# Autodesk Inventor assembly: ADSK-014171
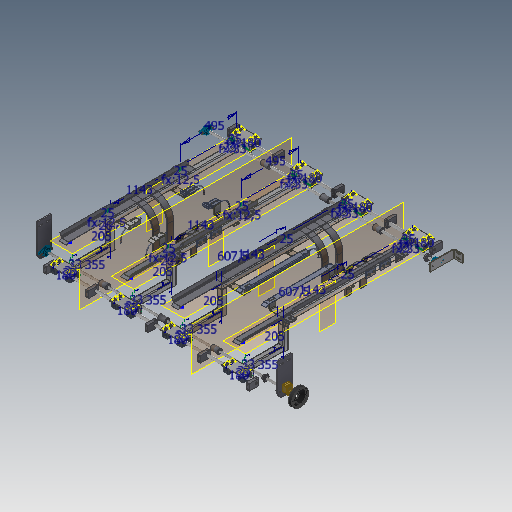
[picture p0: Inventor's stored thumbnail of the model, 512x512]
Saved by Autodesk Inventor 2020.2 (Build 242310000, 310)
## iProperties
Created: 2019-10
Part Number: ADSK-014171
Document SubType Name: Assembly
Designer: lutzd
Mass: 130307 g
Surface Area: 71619.2 cm^2
Volume: 22224.3 cm^3
Density: 5.86325 g/cm^3
VLDS_Profile: Default Assembly
VLDS_TimeStamp: 2016-07-29
VLDS_FailCnt: 0
VLDS_AcceptCnt: 0
Dimensions: 1749x369,4x2340,3 mm
Mass: 130,307 kg
DocNumber: ADSK-014171
Folder: 01 - Themengebiete\Simplification\01 - Packaging machine\
VDS_Category: 3D Komponenten
VDS_NumSchm: Autodesk
Title: SUB-159310
Author: lutzd
Revision Number: -
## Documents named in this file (49)
- D:\07 - DEMODATEN\OTX 2019 - Dataset - UPDATE - Dez2019\Designs\07-Packing machine\ADSK-014171.iam
- D:\07 - DEMODATEN\OTX 2019 - Dataset - UPDATE - Dez2019\Designs\07-Packing machine\Parts\ADSK-011683.ipt
- D:\07 - DEMODATEN\OTX 2019 - Dataset - UPDATE - Dez2019\Designs\07-Packing machine\Parts\ADSK-011686.ipt
- D:\07 - DEMODATEN\OTX 2019 - Dataset - UPDATE - Dez2019\Designs\07-Packing machine\Parts\ADSK-011714.ipt
- D:\07 - DEMODATEN\OTX 2019 - Dataset - UPDATE - Dez2019\Content Center Files\de-DE\DIN 125-1  B\DIN 125-1 - B 8,4.ipt
- D:\07 - DEMODATEN\OTX 2019 - Dataset - UPDATE - Dez2019\Designs\07-Packing machine\Parts\ADSK-011768.ipt
- D:\07 - DEMODATEN\OTX 2019 - Dataset - UPDATE - Dez2019\Designs\07-Packing machine\Parts\ADSK-011336.ipt
- D:\07 - DEMODATEN\OTX 2019 - Dataset - UPDATE - Dez2019\Designs\07-Packing machine\Parts\ADSK-011726.ipt
- D:\07 - DEMODATEN\OTX 2019 - Dataset - UPDATE - Dez2019\Designs\07-Packing machine\Parts\ADSK-011337.ipt
- D:\07 - DEMODATEN\OTX 2019 - Dataset - UPDATE - Dez2019\Designs\07-Packing machine\Parts\ADSK-011339.ipt
- D:\07 - DEMODATEN\OTX 2019 - Dataset - UPDATE - Dez2019\Designs\07-Packing machine\Parts\ADSK-011723.ipt
- D:\07 - DEMODATEN\OTX 2019 - Dataset - UPDATE - Dez2019\Content Center Files\de-DE\ISO 2491 - A\ISO 2491 - A  5 x 3 x 32.ipt
- D:\07 - DEMODATEN\OTX 2019 - Dataset - UPDATE - Dez2019\Designs\07-Packing machine\Parts\ADSK-011309.ipt
- D:\07 - DEMODATEN\OTX 2019 - Dataset - UPDATE - Dez2019\Content Center Files\de-DE\ISO 2491 - A\ISO 2491 - A  5 x 3 x 16.ipt
- D:\07 - DEMODATEN\OTX 2019 - Dataset - UPDATE - Dez2019\Content Center Files\de-DE\ISO 4028\ISO 4028 - M5 x 6 - ISO.ipt
- D:\07 - DEMODATEN\OTX 2019 - Dataset - UPDATE - Dez2019\Content Center Files\de-DE\ISO 4028\ISO 4028 - M5 x 10 - ISO.ipt
- D:\07 - DEMODATEN\OTX 2019 - Dataset - UPDATE - Dez2019\Designs\07-Packing machine\500277.iam
- D:\07 - DEMODATEN\OTX 2019 - Dataset - UPDATE - Dez2019\Designs\07-Packing machine\Parts\ADSK-011325.ipt
- D:\07 - DEMODATEN\OTX 2019 - Dataset - UPDATE - Dez2019\Designs\07-Packing machine\ADSK-014191.iam
- D:\07 - DEMODATEN\OTX 2019 - Dataset - UPDATE - Dez2019\Designs\07-Packing machine\Parts\ADSK-014197.ipt
- D:\07 - DEMODATEN\OTX 2019 - Dataset - UPDATE - Dez2019\Designs\07-Packing machine\Parts\ADSK-011328.ipt
- D:\07 - DEMODATEN\OTX 2019 - Dataset - UPDATE - Dez2019\Content Center Files\de-DE\ISO 4762(2)\ISO 4762 - M8 x 25ISO.ipt
- D:\07 - DEMODATEN\OTX 2019 - Dataset - UPDATE - Dez2019\Content Center Files\de-DE\ISO 4762(2)\ISO 4762 - M8 x 80ISO.ipt
- D:\07 - DEMODATEN\OTX 2019 - Dataset - UPDATE - Dez2019\Content Center Files\de-DE\ISO 4762(2)\ISO 4762 - M8 x 65ISO.ipt
- D:\07 - DEMODATEN\OTX 2019 - Dataset - UPDATE - Dez2019\Content Center Files\de-DE\ISO 4032(1)\ISO 4032 - M8DIN EN.ipt
- D:\07 - DEMODATEN\OTX 2019 - Dataset - UPDATE - Dez2019\Designs\07-Packing machine\Parts\ADSK-011684.ipt
- D:\07 - DEMODATEN\OTX 2019 - Dataset - UPDATE - Dez2019\Designs\07-Packing machine\Parts\ADSK-011685.ipt
- D:\07 - DEMODATEN\OTX 2019 - Dataset - UPDATE - Dez2019\Designs\07-Packing machine\500249.iam
- D:\07 - DEMODATEN\OTX 2019 - Dataset - UPDATE - Dez2019\Designs\07-Packing machine\500382.iam
- D:\07 - DEMODATEN\OTX 2019 - Dataset - UPDATE - Dez2019\Designs\07-Packing machine\500380R.iam
- D:\07 - DEMODATEN\OTX 2019 - Dataset - UPDATE - Dez2019\Designs\07-Packing machine\500380L.iam
- D:\07 - DEMODATEN\OTX 2019 - Dataset - UPDATE - Dez2019\Designs\07-Packing machine\500400R.iam
- D:\07 - DEMODATEN\OTX 2019 - Dataset - UPDATE - Dez2019\Designs\07-Packing machine\500400L.iam
- D:\07 - DEMODATEN\OTX 2019 - Dataset - UPDATE - Dez2019\Designs\07-Packing machine\Parts\ADSK-011326.ipt
- D:\07 - DEMODATEN\OTX 2019 - Dataset - UPDATE - Dez2019\Designs\07-Packing machine\Parts\ADSK-011327.ipt
- D:\07 - DEMODATEN\OTX 2019 - Dataset - UPDATE - Dez2019\Designs\07-Packing machine\500579.iam
- D:\07 - DEMODATEN\OTX 2019 - Dataset - UPDATE - Dez2019\Content Center Files\de-DE\ISO 4762(2)\ISO 4762 - M8 x 16ISO.ipt
- D:\07 - DEMODATEN\OTX 2019 - Dataset - UPDATE - Dez2019\Content Center Files\de-DE\ISO 4762(2)\ISO 4762 - M12 x 30ISO.ipt
- D:\07 - DEMODATEN\OTX 2019 - Dataset - UPDATE - Dez2019\Designs\07-Packing machine\500369.iam
- D:\07 - DEMODATEN\OTX 2019 - Dataset - UPDATE - Dez2019\Designs\07-Packing machine\Parts\ADSK-011509.ipt
- D:\07 - DEMODATEN\OTX 2019 - Dataset - UPDATE - Dez2019\Designs\07-Packing machine\Parts\ADSK-011508.ipt
- D:\07 - DEMODATEN\OTX 2019 - Dataset - UPDATE - Dez2019\Designs\07-Packing machine\Parts\ADSK-011312.ipt
- D:\07 - DEMODATEN\OTX 2019 - Dataset - UPDATE - Dez2019\Content Center Files\de-DE\ISO 4028\ISO 4028 - M5 x 16 - ISO.ipt
- D:\07 - DEMODATEN\OTX 2019 - Dataset - UPDATE - Dez2019\Content Center Files\de-DE\ISO 10642(1)\ISO 10642 - M4x10.ipt
- D:\07 - DEMODATEN\OTX 2019 - Dataset - UPDATE - Dez2019\Designs\07-Packing machine\Parts\ADSK-011510.ipt
- D:\07 - DEMODATEN\OTX 2019 - Dataset - UPDATE - Dez2019\Designs\07-Packing machine\Parts\ADSK-011511.ipt
- D:\07 - DEMODATEN\OTX 2019 - Dataset - UPDATE - Dez2019\Designs\07-Packing machine\Parts\ADSK-011512.ipt
- D:\07 - DEMODATEN\OTX 2019 - Dataset - UPDATE - Dez2019\Content Center Files\de-DE\DIN 125-1  B\DIN 125-1 - B 4,3.ipt
- D:\07 - DEMODATEN\OTX 2019 - Dataset - UPDATE - Dez2019\Content Center Files\de-DE\ISO 4762(2)\ISO 4762 - M4 x 10ISO.ipt
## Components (377 placed, 48 different names)
1. ADSK-011683:1 — Passend:1, Passend:2, Passend:4, Fluchtend:2, Passend:7, Passend:8, Passend:9, Passend:19, Fluchtend:97
2. ADSK-011686:1 — Passend:3, Passend:4, Fluchtend:2, Passend:5, Passend:6, Passend:10, Passend:11, Passend:16, Passend:17, Passend:18, Passend:34
3. ADSK-011714:1 — Passend:6, Passend:10, Passend:11, Fluchtend:104
4. ADSK-011714:2 — Passend:7, Passend:8, Passend:9, Passend:20
5. ADSK-011768:1 — Passend:16, Passend:17, Passend:18, Passend:40
6. ADSK-011336:1 — Passend:19, Passend:20, Passend:26
7. ADSK-011726:1 — Passend:21, Passend:26, Passend:27, Fluchtend:89, Passend:89
8. ADSK-011726:2 — Passend:22, Fluchtend:10, Passend:28, Fluchtend:52, Passend:90
9. ADSK-011726:3 — Passend:23, Passend:29, Passend:31, Fluchtend:51, Passend:88
10. ADSK-011337:1 — Passend:24, Passend:27, Passend:28, Passend:89
11. ADSK-014197:2 — Passend:25, Passend:29, Passend:52, Passend:90
12. ADSK-011339:1 — Passend:30, Passend:31, Passend:33, Passend:36, Passend:37, Passend:38, Passend:39, Passend:42, Passend:44, Fluchtend:44, Fluchtend:45, Passend:45, Tangential:1, Passend:51, Passend:88
13. ADSK-011723:1 — Passend:33, Passend:34, Passend:45, Passend:47, Fluchtend:103, ROTATION
14. ADSK-011309:1 — Passend:39, Passend:40, Fluchtend:45, Passend:46
15. 500277:1 [sub-assembly] — Passend:52, Passend:54, Passend:61, Passend:62, Passend:63, Passend:64, Passend:65, Passend:66, Passend:87, Passend:148, Passend:149, Passend:152, Passend:153, Passend:243, Passend:269, Passend:270, Passend:271, Passend:272, Passend:273, Passend:274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
16. 500277:2 [sub-assembly] — Passend:51, Passend:53, Passend:55, Passend:56, Passend:57, Passend:58, Passend:59, Passend:60, Passend:86, Passend:142, Passend:143, Passend:146, Passend:147, Passend:263, Passend:264, Passend:265, Passend:266, Passend:267, Passend:268, Passend:287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
17. ADSK-011325:1 — Passend:61, Passend:62, Passend:63, Passend:115
18. ADSK-011325:2 — Passend:58, Passend:59, Passend:60
19. ADSK-011325:3 — Passend:55, Passend:56, Passend:57
20. ADSK-011325:4 — Passend:64, Passend:65, Passend:66
21. ADSK-011325:5 — Passend:143, Passend:144, Passend:146
22. ADSK-011325:6 — Passend:142, Passend:145, Passend:147
23. ADSK-011325:7 — Passend:149, Passend:151, Passend:152
24. ADSK-011325:8 — Passend:148, Passend:150, Passend:153
25. ADSK-014191:1 [sub-assembly] — Passend:80, Passend:82, Passend:85, Passend:136, Passend:137, Passend:140, Passend:141, Passend:160, Passend:161, Passend:164, Passend:165, Passend:250, Passend:281, Passend:282, Passend:283, Passend:284, Passend:285, Passend:286, Passend:299, Passend:300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
26. ADSK-014191:2 [sub-assembly] — Passend:79, Passend:81, Passend:84, Passend:130, Passend:132, Passend:133, Passend:135, Passend:154, Passend:155, Passend:158, Passend:159, Passend:275, Passend:276, Passend:277, Passend:278, Passend:279, Passend:280, Passend:305, Passend:306, Passend:307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
27. ADSK-011325:9 — Passend:130, Passend:131, Passend:132
28. ADSK-011325:10 — Passend:133, Passend:134, Passend:135
29. ADSK-011325:11 — Passend:136, Passend:139, Passend:140
30. ADSK-011325:12 — Passend:137, Passend:138, Passend:141
31. ADSK-011325:13 — Passend:155, Passend:156, Passend:159
32. ADSK-011325:14 — Passend:154, Passend:157, Passend:158
33. ADSK-011325:15 — Passend:161, Passend:162, Passend:165
34. ADSK-011325:16 — Passend:160, Passend:163, Passend:164
35. ADSK-011326:3 — Passend:115, Einfügen:8, Fluchtend:90, Passend:124, Passend:125, Passend:126, Passend:131, Passend:134, Passend:138, Passend:139, Einfügen:99
36. ADSK-011327:5 — Winkel:2, Fluchtend:94, Fluchtend:95, Fluchtend:96, Einfügen:99
37. ADSK-011327:6 — Einfügen:8, Winkel:1
38. ADSK-011326:4 — Einfügen:9, Einfügen:10, Passend:117, Passend:118, Passend:119, Passend:120, Passend:144, Passend:145, Passend:150, Passend:151, Passend:156, Passend:157, Passend:162, Passend:163
39. ADSK-011327:7 — Einfügen:9, Winkel:3, Fluchtend:93
40. ADSK-011327:8 — Einfügen:10, Winkel:4
41. ADSK-011328:1 — Passend:118, Fluchtend:91, Fluchtend:93, Passend:121
42. ADSK-011328:2 — Passend:119, Fluchtend:91, Fluchtend:92, Passend:122
43. ADSK-011328:3 — Passend:120, Fluchtend:92, Passend:123
44. ADSK-011328:4 — Passend:124, Fluchtend:96, Passend:127
45. ADSK-011328:5 — Passend:125, Fluchtend:95, Passend:128
46. ADSK-011328:6 — Passend:126, Fluchtend:94, Passend:129
47. ADSK-011714:3 — Fluchtend:97, Passend:250, Passend:258
48. ADSK-011336:2 — Passend:247, Fluchtend:99
49. ADSK-011726:4 — Passend:244, Passend:247, Fluchtend:98
50. ADSK-011726:5 — Passend:245, Passend:246, Fluchtend:100, Fluchtend:102
51. ADSK-011726:6 — Passend:249, Fluchtend:101, Passend:251, Passend:252, Passend:253
52. ADSK-011337:2 — Passend:243, Passend:244, Passend:245
53. ADSK-014197:3 — Passend:246, Passend:248, Passend:249, Fluchtend:102
54. ADSK-011723:2 — Passend:248, Fluchtend:103, ROTATION
55. ADSK-011684:1 — Passend:251, Passend:252, Passend:253, Passend:254, Passend:255, Passend:256, Passend:257
56. ADSK-011714:4 — Passend:257, Fluchtend:104, Passend:258, Passend:259, Passend:260
57. ADSK-011685:1 — Passend:259, Passend:260, Passend:261, Passend:262
58. 500249:1 [sub-assembly] — Passend:269, Passend:270, Passend:271, Passend:364, Passend:366
59. 500249:2 [sub-assembly] — Passend:263, Passend:267, Passend:268, Passend:344, Passend:346
60. 500249:3 [sub-assembly] — Passend:264, Passend:265, Passend:266, Passend:348, Passend:350
61. 500249:4 [sub-assembly] — Passend:275, Passend:276, Passend:277, Passend:380, Passend:382
62. 500249:5 [sub-assembly] — Passend:272, Passend:273, Passend:274, Passend:360, Passend:362
63. 500249:6 [sub-assembly] — Passend:278, Passend:279, Passend:280, Passend:376, Passend:378
64. 500249:7 [sub-assembly] — Passend:282, Passend:285, Passend:286, Passend:392, Passend:394
65. 500249:8 [sub-assembly] — Passend:281, Passend:283, Passend:284, Passend:396, Passend:398
66. 500382:1 [sub-assembly] — Passend:287, Passend:288, Passend:289, Passend:320, Passend:352, Passend:354
67. 500382:2 [sub-assembly] — Passend:290, Passend:291, Passend:292, Passend:318, Passend:319, Passend:340, Passend:342
68. 500382:3 [sub-assembly] — Passend:293, Passend:294, Passend:295, Passend:315, Passend:356, Passend:358
69. 500382:4 [sub-assembly] — Passend:296, Passend:297, Passend:298, Fluchtend:107, Passend:316, Passend:368, Passend:370
70. 500382:5 [sub-assembly] — Passend:299, Passend:301, Passend:302, Passend:311, Passend:312, Passend:400, Passend:402, Fluchtend:435
71. 500382:6 [sub-assembly] — Passend:300, Passend:303, Passend:304, Passend:313, Passend:388, Passend:390
72. 500382:7 [sub-assembly] — Passend:305, Passend:309, Passend:310, Passend:314, Fluchtend:105, Passend:384, Passend:386
73. 500382:8 [sub-assembly] — Passend:306, Passend:307, Passend:308, Passend:317, Passend:372, Passend:374
74. 500380R:1 [sub-assembly] — Passend:311, Passend:312, Passend:313, Passend:327, Passend:539, Passend:541, Fluchtend:435
75. 500380L:1 [sub-assembly] — Passend:314, Fluchtend:105, Passend:317, Passend:326, Passend:330, Passend:535, Passend:537
76. 500400R:1 [sub-assembly] — Passend:315, Fluchtend:107, Passend:316, Passend:325, Fluchtend:108, Passend:543, Passend:545
77. 500400L:1 [sub-assembly] — Passend:318, Passend:319, Passend:320, Passend:328, Passend:547, Passend:549, Passend:550
78. 500579:1 [sub-assembly] — Passend:321, Passend:337, Passend:338, Passend:411, Passend:412, Passend:413, Passend:441, Passend:443
79. 500579:4 [sub-assembly] — Passend:324, Passend:331, Passend:332, Passend:415, Passend:418, Passend:429, Passend:431
80. 500369:1 [sub-assembly] — Passend:406, Passend:407, Passend:408, Passend:414, Passend:419, Fluchtend:111, Passend:421, Fluchtend:423, Passend:437, Passend:439
81. 500369:2 [sub-assembly] — Passend:405, Passend:409, Passend:410, Passend:416, Passend:417, Passend:420, Fluchtend:110, Passend:422, Passend:424, Passend:433, Passend:435
82. ADSK-011509:1 — Passend:411, Passend:412, Passend:413, Passend:414, Fluchtend:424
83. ADSK-011508:1 — Passend:415, Passend:416, Passend:417, Passend:418, Passend:427
84. ADSK-011312:1 — Passend:420, Fluchtend:110, Passend:422, Passend:426
85. ADSK-011312:2 — Passend:419, Fluchtend:111, Passend:421, Fluchtend:423, Passend:425
86. 500369:3 [sub-assembly] — Passend:455, Passend:456, Passend:457, Fluchtend:426, Passend:479, Passend:483, Passend:485, Passend:487, Passend:492, Fluchtend:427, Fluchtend:431, Passend:497, Passend:514, Passend:517, Fluchtend:433
87. 500369:4 [sub-assembly] — Passend:454, Passend:458, Passend:459, Fluchtend:425, Passend:491, Passend:495, Fluchtend:429, Passend:499, Passend:507, Passend:508, Passend:509
88. 500369:5 [sub-assembly] — Passend:453, Passend:462, Passend:463, Passend:465, Passend:467, Passend:471, Passend:473, Passend:475, Passend:493, Passend:494, Fluchtend:432, Passend:496, Passend:515, Passend:516, Fluchtend:434
89. 500369:6 [sub-assembly] — Passend:452, Passend:460, Passend:461, Passend:464, Passend:490, Fluchtend:428, Fluchtend:430, Passend:498, Passend:504, Passend:505, Passend:506
90. ADSK-011312:3 — Passend:492, Fluchtend:427, Fluchtend:431, Passend:500
91. ADSK-011312:4 — Passend:493, Passend:494, Fluchtend:432, Passend:503
92. ADSK-011312:5 — Passend:491, Passend:495, Fluchtend:429, Passend:502
93. ADSK-011312:6 — Passend:490, Fluchtend:428, Fluchtend:430, Passend:501
94. ADSK-011510:1 — Passend:504, Passend:505, Passend:506
95. ADSK-011511:1 — Passend:507, Passend:508, Passend:509
96. ADSK-011512:1 — Passend:514, Passend:517, Fluchtend:433, Passend:523, Passend:525
97. ADSK-011512:2 — Passend:515, Passend:516, Fluchtend:434, Passend:519, Passend:521
98. DIN 125-1 B B 8,4:98 — Einfügen:161
99. DIN 125-1 B B 8,4:99 — Einfügen:162
100. DIN 125-1 B B 4,3:1 — Passend:519, Passend:531, Passend:533
101. DIN 125-1 B B 4,3:2 — Passend:521
102. DIN 125-1 B B 4,3:3 — Passend:523, Passend:527, Passend:529
103. DIN 125-1 B B 4,3:4 — Passend:525
104. ISO 4762 M4 x 10:1 — Passend:527
105. ISO 4762 M4 x 10:2 — Passend:529
106. ISO 4762 M4 x 10:3 — Passend:531
107. ISO 4762 M4 x 10:4 — Passend:533
108. DIN 125-1 B B 8,4:90 — Passend:535
109. DIN 125-1 B B 8,4:91 — Passend:537
110. DIN 125-1 B B 8,4:92 — Passend:539
111. DIN 125-1 B B 8,4:93 — Passend:541
112. DIN 125-1 B B 8,4:94 — Passend:543
113. DIN 125-1 B B 8,4:95 — Passend:545
114. DIN 125-1 B B 8,4:96 — Passend:547
115. DIN 125-1 B B 8,4:97 — Passend:549
116. ISO 4762 M8 x 16:49
117. ISO 4762 M8 x 16:50
118. ISO 4762 M8 x 16:51
119. ISO 4762 M8 x 16:52
120. ISO 4762 M8 x 16:53
121. ISO 4762 M8 x 16:54
122. ISO 4762 M8 x 16:55
123. ISO 4762 M8 x 16:56
124. ISO 10642 M4x10:9
125. ISO 10642 M4x10:10
126. ISO 10642 M4x10:11
127. ISO 10642 M4x10:12
128. DIN 125-1 B B 8,4:79 — Passend:467, Einfügen:143
129. DIN 125-1 B B 8,4:81 — Passend:471
130. DIN 125-1 B B 8,4:82 — Passend:473, Einfügen:146
131. DIN 125-1 B B 8,4:83 — Passend:475, Einfügen:145
132. DIN 125-1 B B 8,4:85 — Passend:479, Einfügen:147
133. DIN 125-1 B B 8,4:87 — Passend:483, Einfügen:148
134. DIN 125-1 B B 8,4:88 — Passend:485, Einfügen:150
135. DIN 125-1 B B 8,4:89 — Passend:487, Einfügen:149
136. ISO 4762 M8 x 16:41 — Einfügen:143
137. ISO 4762 M8 x 16:42
138. ISO 4762 M8 x 16:43 — Einfügen:146
139. ISO 4762 M8 x 16:44 — Einfügen:145
140. ISO 4762 M8 x 16:45 — Einfügen:147
141. ISO 4762 M8 x 16:46 — Einfügen:148
142. ISO 4762 M8 x 16:47 — Einfügen:149
143. ISO 4762 M8 x 16:48 — Einfügen:150
144. ISO 4028 M5 x 16:3 — Passend:497, Passend:500
145. ISO 4028 M5 x 16:4 — Passend:496, Passend:503
146. ISO 4028 M5 x 16:5 — Passend:499, Passend:502
147. ISO 4028 M5 x 16:6 — Passend:498, Passend:501
148. ISO 4028 M5 x 16:1 — Passend:425
149. ISO 4028 M5 x 16:2 — Passend:424, Passend:426
150. DIN 125-1 B B 8,4:71 — Passend:429, Einfügen:142
151. DIN 125-1 B B 8,4:72 — Passend:431, Einfügen:141
152. DIN 125-1 B B 8,4:73 — Passend:433, Einfügen:140
153. DIN 125-1 B B 8,4:74 — Passend:435, Einfügen:139
154. DIN 125-1 B B 8,4:75 — Passend:437, Einfügen:138
155. DIN 125-1 B B 8,4:76 — Passend:439, Einfügen:137
156. DIN 125-1 B B 8,4:77 — Passend:441, Einfügen:136
157. DIN 125-1 B B 8,4:78 — Passend:443, Einfügen:135
158. ISO 4762 M8 x 16:33 — Einfügen:135
159. ISO 4762 M8 x 16:34 — Einfügen:136
160. ISO 4762 M8 x 16:35 — Einfügen:138
161. ISO 4762 M8 x 16:36 — Einfügen:137
162. ISO 4762 M8 x 16:37 — Einfügen:142
163. ISO 4762 M8 x 16:38 — Einfügen:141
164. ISO 4762 M8 x 16:39 — Einfügen:140
165. ISO 4762 M8 x 16:40 — Einfügen:139
166. ISO 10642 M4x10:1
167. ISO 10642 M4x10:2
168. ISO 10642 M4x10:3
169. ISO 10642 M4x10:4
170. ISO 10642 M4x10:5
171. ISO 10642 M4x10:6
172. ISO 10642 M4x10:7
173. ISO 10642 M4x10:8
174. DIN 125-1 B B 8,4:39 — Passend:340, Einfügen:123
175. DIN 125-1 B B 8,4:40 — Passend:342, Einfügen:124
176. DIN 125-1 B B 8,4:41 — Passend:344, Einfügen:125
177. DIN 125-1 B B 8,4:42 — Passend:346, Einfügen:126
178. DIN 125-1 B B 8,4:43 — Passend:348, Einfügen:127
179. DIN 125-1 B B 8,4:44 — Passend:350, Einfügen:128
180. DIN 125-1 B B 8,4:45 — Passend:352, Einfügen:129
181. DIN 125-1 B B 8,4:46 — Passend:354, Einfügen:130
182. DIN 125-1 B B 8,4:47 — Passend:356, Einfügen:122
183. DIN 125-1 B B 8,4:48 — Passend:358, Einfügen:121
184. DIN 125-1 B B 8,4:49 — Passend:360, Einfügen:120
185. DIN 125-1 B B 8,4:50 — Passend:362, Einfügen:119
186. DIN 125-1 B B 8,4:51 — Passend:364, Einfügen:118
187. DIN 125-1 B B 8,4:52 — Passend:366, Einfügen:117
188. DIN 125-1 B B 8,4:53 — Passend:368, Einfügen:116
189. DIN 125-1 B B 8,4:54 — Passend:370, Einfügen:115
190. DIN 125-1 B B 8,4:55 — Passend:372, Einfügen:107
191. DIN 125-1 B B 8,4:56 — Passend:374, Einfügen:108
192. DIN 125-1 B B 8,4:57 — Passend:376, Einfügen:109
193. DIN 125-1 B B 8,4:58 — Passend:378, Einfügen:110
194. DIN 125-1 B B 8,4:59 — Passend:380, Einfügen:111
195. DIN 125-1 B B 8,4:60 — Passend:382, Einfügen:112
196. DIN 125-1 B B 8,4:61 — Passend:384, Einfügen:113
197. DIN 125-1 B B 8,4:62 — Passend:386, Einfügen:114
198. DIN 125-1 B B 8,4:63 — Passend:388, Einfügen:106
199. DIN 125-1 B B 8,4:64 — Passend:390, Einfügen:105
200. DIN 125-1 B B 8,4:65 — Passend:392, Einfügen:104
201. DIN 125-1 B B 8,4:66 — Passend:394, Einfügen:103
202. DIN 125-1 B B 8,4:67 — Passend:396, Einfügen:102
203. DIN 125-1 B B 8,4:68 — Passend:398, Einfügen:101
204. DIN 125-1 B B 8,4:69 — Passend:400, Einfügen:100
205. DIN 125-1 B B 8,4:70 — Passend:402, Passend:404
206. ISO 4762 M8 x 16:1 — Passend:404
207. ISO 4762 M8 x 16:2 — Einfügen:100
208. ISO 4762 M8 x 16:3 — Einfügen:101
209. ISO 4762 M8 x 16:4 — Einfügen:102
210. ISO 4762 M8 x 16:5 — Einfügen:103
211. ISO 4762 M8 x 16:6 — Einfügen:104
212. ISO 4762 M8 x 16:7 — Einfügen:106
213. ISO 4762 M8 x 16:8 — Einfügen:105
214. ISO 4762 M8 x 16:9 — Einfügen:107
215. ISO 4762 M8 x 16:10 — Einfügen:108
216. ISO 4762 M8 x 16:11 — Einfügen:109
217. ISO 4762 M8 x 16:12 — Einfügen:110
218. ISO 4762 M8 x 16:13 — Einfügen:111
219. ISO 4762 M8 x 16:14 — Einfügen:112
220. ISO 4762 M8 x 16:15 — Einfügen:113
221. ISO 4762 M8 x 16:16 — Einfügen:114
222. ISO 4762 M8 x 16:17 — Einfügen:115
223. ISO 4762 M8 x 16:18 — Einfügen:116
224. ISO 4762 M8 x 16:19 — Einfügen:117
225. ISO 4762 M8 x 16:20 — Einfügen:118
226. ISO 4762 M8 x 16:21 — Einfügen:119
227. ISO 4762 M8 x 16:22 — Einfügen:120
228. ISO 4762 M8 x 16:23 — Einfügen:121
229. ISO 4762 M8 x 16:24 — Einfügen:122
230. ISO 4762 M8 x 16:25 — Einfügen:123
231. ISO 4762 M8 x 16:26 — Einfügen:124
232. ISO 4762 M8 x 16:27 — Einfügen:125
233. ISO 4762 M8 x 16:28 — Einfügen:126
234. ISO 4762 M8 x 16:29 — Einfügen:127
235. ISO 4762 M8 x 16:30 — Einfügen:128
236. ISO 4762 M8 x 16:31 — Einfügen:129
237. ISO 4762 M8 x 16:32 — Einfügen:130
238. ISO 4762 M12 x 30:1
239. ISO 4762 M12 x 30:2
240. ISO 4762 M12 x 30:3
241. ISO 4762 M12 x 30:4
242. DIN 125-1 B B 8,4:37
243. DIN 125-1 B B 8,4:38
244. ISO 4762 M8 x 25:7 — Passend:262
245. ISO 4762 M8 x 25:8 — Passend:261
246. ISO 2491 A A  5 x 3 x 32:2 — Passend:254, Passend:255, Passend:256
247. ISO 4028 M5 x 10:2
248. ISO 4762 M8 x 25:5 — Einfügen:162
249. ISO 4762 M8 x 25:6 — Einfügen:161
250. DIN 125-1 B B 8,4:5
251. DIN 125-1 B B 8,4:6
252. DIN 125-1 B B 8,4:7
253. DIN 125-1 B B 8,4:8
254. DIN 125-1 B B 8,4:9
255. DIN 125-1 B B 8,4:10
256. DIN 125-1 B B 8,4:11
257. DIN 125-1 B B 8,4:12
258. DIN 125-1 B B 8,4:13
259. DIN 125-1 B B 8,4:14
260. DIN 125-1 B B 8,4:15
261. DIN 125-1 B B 8,4:16
262. DIN 125-1 B B 8,4:17
263. DIN 125-1 B B 8,4:18
264. DIN 125-1 B B 8,4:19
265. DIN 125-1 B B 8,4:20
266. DIN 125-1 B B 8,4:21
267. DIN 125-1 B B 8,4:22
268. DIN 125-1 B B 8,4:23
269. DIN 125-1 B B 8,4:24
270. DIN 125-1 B B 8,4:25
271. DIN 125-1 B B 8,4:26
272. DIN 125-1 B B 8,4:27
273. DIN 125-1 B B 8,4:28
274. DIN 125-1 B B 8,4:29
275. DIN 125-1 B B 8,4:30
276. DIN 125-1 B B 8,4:31
277. DIN 125-1 B B 8,4:32
278. DIN 125-1 B B 8,4:33
279. DIN 125-1 B B 8,4:34
280. DIN 125-1 B B 8,4:35
281. DIN 125-1 B B 8,4:36
282. DIN EN 24032 M8:1
283. DIN EN 24032 M8:2
284. DIN EN 24032 M8:3
285. DIN EN 24032 M8:4
286. DIN EN 24032 M8:5
287. DIN EN 24032 M8:6
288. DIN EN 24032 M8:7
289. DIN EN 24032 M8:8
290. DIN EN 24032 M8:9
291. DIN EN 24032 M8:10
292. DIN EN 24032 M8:11
293. DIN EN 24032 M8:12
294. DIN EN 24032 M8:13
295. DIN EN 24032 M8:14
296. DIN EN 24032 M8:15
297. DIN EN 24032 M8:16
298. DIN EN 24032 M8:17
299. DIN EN 24032 M8:18
300. DIN EN 24032 M8:19
301. DIN EN 24032 M8:20
302. DIN EN 24032 M8:21
303. DIN EN 24032 M8:22
304. DIN EN 24032 M8:23
305. DIN EN 24032 M8:24
306. DIN EN 24032 M8:25
307. DIN EN 24032 M8:26
308. DIN EN 24032 M8:27
309. DIN EN 24032 M8:28
310. DIN EN 24032 M8:29
311. DIN EN 24032 M8:30
312. DIN EN 24032 M8:31
313. DIN EN 24032 M8:32
314. ISO 4762 M8 x 65:1
315. ISO 4762 M8 x 65:2
316. ISO 4762 M8 x 65:3
317. ISO 4762 M8 x 65:4
318. ISO 4762 M8 x 65:5
319. ISO 4762 M8 x 65:6
320. ISO 4762 M8 x 65:7
321. ISO 4762 M8 x 65:8
322. ISO 4762 M8 x 65:9
323. ISO 4762 M8 x 65:10
324. ISO 4762 M8 x 65:11
325. ISO 4762 M8 x 65:12
326. ISO 4762 M8 x 65:13
327. ISO 4762 M8 x 65:14
328. ISO 4762 M8 x 65:15
329. ISO 4762 M8 x 65:16
330. ISO 4762 M8 x 65:17
331. ISO 4762 M8 x 65:18
332. ISO 4762 M8 x 65:19
333. ISO 4762 M8 x 65:20
334. ISO 4762 M8 x 65:21
335. ISO 4762 M8 x 65:22
336. ISO 4762 M8 x 65:23
337. ISO 4762 M8 x 65:24
338. ISO 4762 M8 x 65:25
339. ISO 4762 M8 x 65:26
340. ISO 4762 M8 x 65:27
341. ISO 4762 M8 x 65:28
342. ISO 4762 M8 x 65:29
343. ISO 4762 M8 x 65:30
344. ISO 4762 M8 x 65:31
345. ISO 4762 M8 x 65:32
346. ISO 4762 M8 x 80:1
347. ISO 4762 M8 x 80:2
348. ISO 4762 M8 x 80:3
349. ISO 4762 M8 x 80:4
350. ISO 4762 M8 x 80:5
351. ISO 4762 M8 x 80:6
352. ISO 4762 M8 x 80:7
353. ISO 4762 M8 x 80:8
354. ISO 4762 M8 x 80:9
355. ISO 4762 M8 x 80:10
356. ISO 4762 M8 x 80:11
357. ISO 4762 M8 x 80:12
358. ISO 4762 M8 x 80:13
359. ISO 4762 M8 x 80:14
360. ISO 4762 M8 x 80:15
361. ISO 4762 M8 x 80:16
362. ISO 4762 M8 x 80:17
363. ISO 4762 M8 x 80:18
364. ISO 4762 M8 x 80:19
365. ISO 4762 M8 x 80:20
366. DIN 125-1 B B 8,4:1 — Einfügen:5
367. DIN 125-1 B B 8,4:2 — Einfügen:6
368. DIN 125-1 B B 8,4:3 — Passend:13, Passend:15
369. DIN 125-1 B B 8,4:4
370. ISO 4762 M8 x 25:1 — Passend:13
371. ISO 4762 M8 x 25:2 — Passend:15
372. ISO 4762 M8 x 25:3 — Einfügen:6
373. ISO 4762 M8 x 25:4 — Einfügen:5
374. ISO 2491 A A  5 x 3 x 32:1 — Passend:36, Passend:37, Passend:38, Passend:48
375. ISO 2491 A A  5 x 3 x 16:1 — Passend:42, Fluchtend:44, Passend:44
376. ISO 4028 M5 x 6:1 — Passend:46, Tangential:1
377. ISO 4028 M5 x 10:1 — Passend:47, Passend:48
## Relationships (434: Mate 334, Insert 54, Flush 40, Angle 4, RelateRotation 1, Tangent 1)
- ROTATION [RelateRotation]: ADSK-011723:1 ↔ ADSK-011723:2
- Passend:1 [Mate]: ADSK-011683:1
- Passend:2 [Mate]: ADSK-011683:1
- Passend:3 [Mate]: ADSK-011686:1
- Passend:4 [Mate]: ADSK-011683:1 ↔ ADSK-011686:1
- Fluchtend:2 [Flush]: ADSK-011683:1 ↔ ADSK-011686:1
- Passend:5 [Mate]: ADSK-011686:1
- Passend:6 [Mate]: ADSK-011686:1 ↔ ADSK-011714:1
- Passend:7 [Mate]: ADSK-011683:1 ↔ ADSK-011714:2
- Passend:8 [Mate]: ADSK-011683:1 ↔ ADSK-011714:2
- Passend:9 [Mate]: ADSK-011683:1 ↔ ADSK-011714:2
- Passend:10 [Mate]: ADSK-011686:1 ↔ ADSK-011714:1
- Passend:11 [Mate]: ADSK-011686:1 ↔ ADSK-011714:1
- Passend:13 [Mate]: DIN 125-1 B B 8,4:3 ↔ ISO 4762 M8 x 25:1
- Passend:15 [Mate]: DIN 125-1 B B 8,4:3 ↔ ISO 4762 M8 x 25:2
- Einfügen:5 [Insert]: DIN 125-1 B B 8,4:1 ↔ ISO 4762 M8 x 25:4
- Einfügen:6 [Insert]: DIN 125-1 B B 8,4:2 ↔ ISO 4762 M8 x 25:3
- Passend:16 [Mate]: ADSK-011686:1 ↔ ADSK-011768:1
- Passend:17 [Mate]: ADSK-011686:1 ↔ ADSK-011768:1
- Passend:18 [Mate]: ADSK-011686:1 ↔ ADSK-011768:1
- Passend:19 [Mate]: ADSK-011683:1 ↔ ADSK-011336:1
- Passend:20 [Mate]: ADSK-011714:2 ↔ ADSK-011336:1
- Passend:21 [Mate]: ADSK-011726:1
- Passend:22 [Mate]: ADSK-011726:2
- Passend:23 [Mate]: ADSK-011726:3
- Fluchtend:10 [Flush]: ADSK-011726:2
- Passend:24 [Mate]: ADSK-011337:1
- Passend:25 [Mate]: ADSK-014197:2
- Passend:26 [Mate]: ADSK-011336:1 ↔ ADSK-011726:1
- Passend:27 [Mate]: ADSK-011726:1 ↔ ADSK-011337:1
- Passend:28 [Mate]: ADSK-011726:2 ↔ ADSK-011337:1
- Passend:29 [Mate]: ADSK-011726:3 ↔ ADSK-014197:2
- Passend:30 [Mate]: ADSK-011339:1
- Passend:31 [Mate]: ADSK-011726:3 ↔ ADSK-011339:1
- Passend:33 [Mate]: ADSK-011339:1 ↔ ADSK-011723:1
- Passend:34 [Mate]: ADSK-011686:1 ↔ ADSK-011723:1
- Passend:36 [Mate]: ADSK-011339:1 ↔ ISO 2491 A A  5 x 3 x 32:1
- Passend:37 [Mate]: ADSK-011339:1 ↔ ISO 2491 A A  5 x 3 x 32:1
- Passend:38 [Mate]: ADSK-011339:1 ↔ ISO 2491 A A  5 x 3 x 32:1
- Passend:39 [Mate]: ADSK-011339:1 ↔ ADSK-011309:1
- Passend:40 [Mate]: ADSK-011768:1 ↔ ADSK-011309:1
- Passend:42 [Mate]: ADSK-011339:1 ↔ ISO 2491 A A  5 x 3 x 16:1
- Fluchtend:44 [Flush]: ADSK-011339:1 ↔ ISO 2491 A A  5 x 3 x 16:1
- Passend:44 [Mate]: ADSK-011339:1 ↔ ISO 2491 A A  5 x 3 x 16:1
- Fluchtend:45 [Flush]: ADSK-011339:1 ↔ ADSK-011309:1
- Passend:45 [Mate]: ADSK-011339:1 ↔ ADSK-011723:1
- Passend:46 [Mate]: ADSK-011309:1 ↔ ISO 4028 M5 x 6:1
- Tangential:1: ADSK-011339:1 ↔ ISO 4028 M5 x 6:1
- Passend:47 [Mate]: ADSK-011723:1 ↔ ISO 4028 M5 x 10:1
- Passend:48 [Mate]: ISO 2491 A A  5 x 3 x 32:1 ↔ ISO 4028 M5 x 10:1
- Passend:51 [Mate]: ADSK-011339:1 ↔ 500277:2
- Passend:52 [Mate]: ADSK-014197:2 ↔ 500277:1
- Passend:53 [Mate]: 500277:2
- Passend:54 [Mate]: 500277:1
- Passend:55 [Mate]: 500277:2 ↔ ADSK-011325:3
- Passend:56 [Mate]: 500277:2 ↔ ADSK-011325:3
- Passend:57 [Mate]: 500277:2 ↔ ADSK-011325:3
- Passend:58 [Mate]: 500277:2 ↔ ADSK-011325:2
- Passend:59 [Mate]: 500277:2 ↔ ADSK-011325:2
- Passend:60 [Mate]: 500277:2 ↔ ADSK-011325:2
- Passend:61 [Mate]: 500277:1 ↔ ADSK-011325:1
- Passend:62 [Mate]: 500277:1 ↔ ADSK-011325:1
- Passend:63 [Mate]: 500277:1 ↔ ADSK-011325:1
- Passend:64 [Mate]: 500277:1 ↔ ADSK-011325:4
- Passend:65 [Mate]: 500277:1 ↔ ADSK-011325:4
- Passend:66 [Mate]: 500277:1 ↔ ADSK-011325:4
- Passend:79 [Mate]: ADSK-014191:2
- Passend:80 [Mate]: ADSK-014191:1
- Passend:81 [Mate]: ADSK-014191:2
- Passend:82 [Mate]: ADSK-014191:1
- Passend:84 [Mate]: ADSK-014191:2
- Passend:85 [Mate]: ADSK-014191:1
- Passend:86 [Mate]: 500277:2
- Passend:87 [Mate]: 500277:1
- Fluchtend:89 [Flush]: ADSK-011726:1
- Fluchtend:51 [Flush]: ADSK-011726:3
- Fluchtend:52 [Flush]: ADSK-011726:2
- Passend:88 [Mate]: ADSK-011726:3 ↔ ADSK-011339:1
- Passend:89 [Mate]: ADSK-011726:1 ↔ ADSK-011337:1
- Passend:90 [Mate]: ADSK-011726:2 ↔ ADSK-014197:2
- Passend:115 [Mate]: ADSK-011325:1 ↔ ADSK-011326:3
- Einfügen:8 [Insert]: ADSK-011326:3 ↔ ADSK-011327:6
- Winkel:1 [Angle]: ADSK-011327:6
- Winkel:2 [Angle]: ADSK-011327:5
- Fluchtend:90 [Flush]: ADSK-011326:3
- Einfügen:9 [Insert]: ADSK-011326:4 ↔ ADSK-011327:7
- Einfügen:10 [Insert]: ADSK-011326:4 ↔ ADSK-011327:8
- Passend:117 [Mate]: ADSK-011326:4
- Winkel:3 [Angle]: ADSK-011327:7
- Winkel:4 [Angle]: ADSK-011327:8
- Passend:118 [Mate]: ADSK-011326:4 ↔ ADSK-011328:1
- Passend:119 [Mate]: ADSK-011326:4 ↔ ADSK-011328:2
- Passend:120 [Mate]: ADSK-011326:4 ↔ ADSK-011328:3
- Fluchtend:91 [Flush]: ADSK-011328:1 ↔ ADSK-011328:2
- Fluchtend:92 [Flush]: ADSK-011328:2 ↔ ADSK-011328:3
- Fluchtend:93 [Flush]: ADSK-011327:7 ↔ ADSK-011328:1
- Passend:121 [Mate]: ADSK-011328:1
- Passend:122 [Mate]: ADSK-011328:2
- Passend:123 [Mate]: ADSK-011328:3
- Passend:124 [Mate]: ADSK-011326:3 ↔ ADSK-011328:4
- Passend:125 [Mate]: ADSK-011326:3 ↔ ADSK-011328:5
- Passend:126 [Mate]: ADSK-011326:3 ↔ ADSK-011328:6
- Fluchtend:94 [Flush]: ADSK-011327:5 ↔ ADSK-011328:6
- Fluchtend:95 [Flush]: ADSK-011327:5 ↔ ADSK-011328:5
- Fluchtend:96 [Flush]: ADSK-011327:5 ↔ ADSK-011328:4
- Passend:127 [Mate]: ADSK-011328:4
- Passend:128 [Mate]: ADSK-011328:5
- Passend:129 [Mate]: ADSK-011328:6
- Passend:130 [Mate]: ADSK-014191:2 ↔ ADSK-011325:9
- Passend:131 [Mate]: ADSK-011325:9 ↔ ADSK-011326:3
- Passend:132 [Mate]: ADSK-014191:2 ↔ ADSK-011325:9
- Passend:133 [Mate]: ADSK-014191:2 ↔ ADSK-011325:10
- Passend:134 [Mate]: ADSK-011325:10 ↔ ADSK-011326:3
- Passend:135 [Mate]: ADSK-014191:2 ↔ ADSK-011325:10
- Passend:136 [Mate]: ADSK-014191:1 ↔ ADSK-011325:11
- Passend:137 [Mate]: ADSK-014191:1 ↔ ADSK-011325:12
- Passend:138 [Mate]: ADSK-011325:12 ↔ ADSK-011326:3
- Passend:139 [Mate]: ADSK-011325:11 ↔ ADSK-011326:3
- Passend:140 [Mate]: ADSK-014191:1 ↔ ADSK-011325:11
- Passend:141 [Mate]: ADSK-014191:1 ↔ ADSK-011325:12
- Passend:142 [Mate]: 500277:2 ↔ ADSK-011325:6
- Passend:143 [Mate]: 500277:2 ↔ ADSK-011325:5
- Passend:144 [Mate]: ADSK-011325:5 ↔ ADSK-011326:4
- Passend:145 [Mate]: ADSK-011325:6 ↔ ADSK-011326:4
- Passend:146 [Mate]: 500277:2 ↔ ADSK-011325:5
- Passend:147 [Mate]: 500277:2 ↔ ADSK-011325:6
- Passend:148 [Mate]: 500277:1 ↔ ADSK-011325:8
- Passend:149 [Mate]: 500277:1 ↔ ADSK-011325:7
- Passend:150 [Mate]: ADSK-011325:8 ↔ ADSK-011326:4
- Passend:151 [Mate]: ADSK-011325:7 ↔ ADSK-011326:4
- Passend:152 [Mate]: 500277:1 ↔ ADSK-011325:7
- Passend:153 [Mate]: 500277:1 ↔ ADSK-011325:8
- Passend:154 [Mate]: ADSK-014191:2 ↔ ADSK-011325:14
- Passend:155 [Mate]: ADSK-014191:2 ↔ ADSK-011325:13
- Passend:156 [Mate]: ADSK-011325:13 ↔ ADSK-011326:4
- Passend:157 [Mate]: ADSK-011325:14 ↔ ADSK-011326:4
- Passend:158 [Mate]: ADSK-014191:2 ↔ ADSK-011325:14
- Passend:159 [Mate]: ADSK-014191:2 ↔ ADSK-011325:13
- Passend:160 [Mate]: ADSK-014191:1 ↔ ADSK-011325:16
- Passend:161 [Mate]: ADSK-014191:1 ↔ ADSK-011325:15
- Passend:162 [Mate]: ADSK-011325:15 ↔ ADSK-011326:4
- Passend:163 [Mate]: ADSK-011325:16 ↔ ADSK-011326:4
- Passend:164 [Mate]: ADSK-014191:1 ↔ ADSK-011325:16
- Passend:165 [Mate]: ADSK-014191:1 ↔ ADSK-011325:15
- Passend:243 [Mate]: 500277:1 ↔ ADSK-011337:2
- Passend:244 [Mate]: ADSK-011726:4 ↔ ADSK-011337:2
- Passend:245 [Mate]: ADSK-011726:5 ↔ ADSK-011337:2
- Passend:246 [Mate]: ADSK-011726:5 ↔ ADSK-014197:3
- Passend:247 [Mate]: ADSK-011336:2 ↔ ADSK-011726:4
- Fluchtend:97 [Flush]: ADSK-011683:1 ↔ ADSK-011714:3
- Passend:248 [Mate]: ADSK-014197:3 ↔ ADSK-011723:2
- Passend:249 [Mate]: ADSK-011726:6 ↔ ADSK-014197:3
- Passend:250 [Mate]: ADSK-014191:1 ↔ ADSK-011714:3
- Fluchtend:98 [Flush]: ADSK-011726:4
- Fluchtend:99 [Flush]: ADSK-011336:2
- Fluchtend:100 [Flush]: ADSK-011726:5
- Fluchtend:101 [Flush]: ADSK-011726:6
- Fluchtend:102 [Flush]: ADSK-011726:5 ↔ ADSK-014197:3
- Passend:251 [Mate]: ADSK-011726:6 ↔ ADSK-011684:1
- Passend:252 [Mate]: ADSK-011726:6 ↔ ADSK-011684:1
- Passend:253 [Mate]: ADSK-011726:6 ↔ ADSK-011684:1
- Fluchtend:103 [Flush]: ADSK-011723:1 ↔ ADSK-011723:2
- Passend:254 [Mate]: ADSK-011684:1 ↔ ISO 2491 A A  5 x 3 x 32:2
- Passend:255 [Mate]: ADSK-011684:1 ↔ ISO 2491 A A  5 x 3 x 32:2
- Passend:256 [Mate]: ADSK-011684:1 ↔ ISO 2491 A A  5 x 3 x 32:2
- Passend:257 [Mate]: ADSK-011684:1 ↔ ADSK-011714:4
- Fluchtend:104 [Flush]: ADSK-011714:1 ↔ ADSK-011714:4
- Passend:258 [Mate]: ADSK-011714:3 ↔ ADSK-011714:4
- Passend:259 [Mate]: ADSK-011714:4 ↔ ADSK-011685:1
- Passend:260 [Mate]: ADSK-011714:4 ↔ ADSK-011685:1
- Passend:261 [Mate]: ADSK-011685:1 ↔ ISO 4762 M8 x 25:8
- Passend:262 [Mate]: ADSK-011685:1 ↔ ISO 4762 M8 x 25:7
- Passend:263 [Mate]: 500277:2 ↔ 500249:2
- Passend:264 [Mate]: 500277:2 ↔ 500249:3
- Passend:265 [Mate]: 500277:2 ↔ 500249:3
- Passend:266 [Mate]: 500277:2 ↔ 500249:3
- Passend:267 [Mate]: 500277:2 ↔ 500249:2
- Passend:268 [Mate]: 500277:2 ↔ 500249:2
- Passend:269 [Mate]: 500277:1 ↔ 500249:1
- Passend:270 [Mate]: 500277:1 ↔ 500249:1
- Passend:271 [Mate]: 500277:1 ↔ 500249:1
- Passend:272 [Mate]: 500277:1 ↔ 500249:5
- Passend:273 [Mate]: 500277:1 ↔ 500249:5
- Passend:274 [Mate]: 500277:1 ↔ 500249:5
- Passend:275 [Mate]: ADSK-014191:2 ↔ 500249:4
- Passend:276 [Mate]: ADSK-014191:2 ↔ 500249:4
- Passend:277 [Mate]: ADSK-014191:2 ↔ 500249:4
- Passend:278 [Mate]: ADSK-014191:2 ↔ 500249:6
- Passend:279 [Mate]: ADSK-014191:2 ↔ 500249:6
- Passend:280 [Mate]: ADSK-014191:2 ↔ 500249:6
- Passend:281 [Mate]: ADSK-014191:1 ↔ 500249:8
- Passend:282 [Mate]: ADSK-014191:1 ↔ 500249:7
- Passend:283 [Mate]: ADSK-014191:1 ↔ 500249:8
- Passend:284 [Mate]: ADSK-014191:1 ↔ 500249:8
- Passend:285 [Mate]: ADSK-014191:1 ↔ 500249:7
- Passend:286 [Mate]: ADSK-014191:1 ↔ 500249:7
- Passend:287 [Mate]: 500277:2 ↔ 500382:1
- Passend:288 [Mate]: 500277:2 ↔ 500382:1
- Passend:289 [Mate]: 500277:2 ↔ 500382:1
- Passend:290 [Mate]: 500277:2 ↔ 500382:2
- Passend:291 [Mate]: 500277:2 ↔ 500382:2
- Passend:292 [Mate]: 500277:2 ↔ 500382:2
- Passend:293 [Mate]: 500277:1 ↔ 500382:3
- Passend:294 [Mate]: 500277:1 ↔ 500382:3
- Passend:295 [Mate]: 500277:1 ↔ 500382:3
- Passend:296 [Mate]: 500277:1 ↔ 500382:4
- Passend:297 [Mate]: 500277:1 ↔ 500382:4
- Passend:298 [Mate]: 500277:1 ↔ 500382:4
- Passend:299 [Mate]: ADSK-014191:1 ↔ 500382:5
- Passend:300 [Mate]: ADSK-014191:1 ↔ 500382:6
- Passend:301 [Mate]: ADSK-014191:1 ↔ 500382:5
- Passend:302 [Mate]: ADSK-014191:1 ↔ 500382:5
- Passend:303 [Mate]: ADSK-014191:1 ↔ 500382:6
- Passend:304 [Mate]: ADSK-014191:1 ↔ 500382:6
- Passend:305 [Mate]: ADSK-014191:2 ↔ 500382:7
- Passend:306 [Mate]: ADSK-014191:2 ↔ 500382:8
- Passend:307 [Mate]: ADSK-014191:2 ↔ 500382:8
- Passend:308 [Mate]: ADSK-014191:2 ↔ 500382:8
- Passend:309 [Mate]: ADSK-014191:2 ↔ 500382:7
- Passend:310 [Mate]: ADSK-014191:2 ↔ 500382:7
- Passend:311 [Mate]: 500382:5 ↔ 500380R:1
- Passend:312 [Mate]: 500382:5 ↔ 500380R:1
- Passend:313 [Mate]: 500382:6 ↔ 500380R:1
- Passend:314 [Mate]: 500382:7 ↔ 500380L:1
- Fluchtend:105 [Flush]: 500382:7 ↔ 500380L:1
- Passend:315 [Mate]: 500382:3 ↔ 500400R:1
- Fluchtend:107 [Flush]: 500382:4 ↔ 500400R:1
- Passend:316 [Mate]: 500382:4 ↔ 500400R:1
- Passend:317 [Mate]: 500382:8 ↔ 500380L:1
- Passend:318 [Mate]: 500382:2 ↔ 500400L:1
- Passend:319 [Mate]: 500382:2 ↔ 500400L:1
- Passend:320 [Mate]: 500382:1 ↔ 500400L:1
- Einfügen:99 [Insert]: ADSK-011326:3 ↔ ADSK-011327:5
- Passend:321 [Mate]: 500277:1 ↔ 500579:1
- Passend:324 [Mate]: 500277:2 ↔ 500579:4
- Passend:325 [Mate]: 500277:1 ↔ 500400R:1
- Passend:326 [Mate]: ADSK-014191:2 ↔ 500380L:1
- Passend:327 [Mate]: ADSK-014191:1 ↔ 500380R:1
- Passend:328 [Mate]: 500277:2 ↔ 500400L:1
- Fluchtend:108 [Flush]: 500400R:1
- Passend:330 [Mate]: 500380L:1
- Passend:331 [Mate]: 500277:2 ↔ 500579:4
- Passend:332 [Mate]: 500277:2 ↔ 500579:4
- Passend:337 [Mate]: 500277:1 ↔ 500579:1
- Passend:338 [Mate]: 500277:1 ↔ 500579:1
- Passend:340 [Mate]: 500382:2 ↔ DIN 125-1 B B 8,4:39
- Passend:342 [Mate]: 500382:2 ↔ DIN 125-1 B B 8,4:40
- Passend:344 [Mate]: 500249:2 ↔ DIN 125-1 B B 8,4:41
- Passend:346 [Mate]: 500249:2 ↔ DIN 125-1 B B 8,4:42
- Passend:348 [Mate]: 500249:3 ↔ DIN 125-1 B B 8,4:43
- Passend:350 [Mate]: 500249:3 ↔ DIN 125-1 B B 8,4:44
- Passend:352 [Mate]: 500382:1 ↔ DIN 125-1 B B 8,4:45
- Passend:354 [Mate]: 500382:1 ↔ DIN 125-1 B B 8,4:46
- Passend:356 [Mate]: 500382:3 ↔ DIN 125-1 B B 8,4:47
- Passend:358 [Mate]: 500382:3 ↔ DIN 125-1 B B 8,4:48
- Passend:360 [Mate]: 500249:5 ↔ DIN 125-1 B B 8,4:49
- Passend:362 [Mate]: 500249:5 ↔ DIN 125-1 B B 8,4:50
- Passend:364 [Mate]: 500249:1 ↔ DIN 125-1 B B 8,4:51
- Passend:366 [Mate]: 500249:1 ↔ DIN 125-1 B B 8,4:52
- Passend:368 [Mate]: 500382:4 ↔ DIN 125-1 B B 8,4:53
- Passend:370 [Mate]: 500382:4 ↔ DIN 125-1 B B 8,4:54
- Passend:372 [Mate]: 500382:8 ↔ DIN 125-1 B B 8,4:55
- Passend:374 [Mate]: 500382:8 ↔ DIN 125-1 B B 8,4:56
- Passend:376 [Mate]: 500249:6 ↔ DIN 125-1 B B 8,4:57
- Passend:378 [Mate]: 500249:6 ↔ DIN 125-1 B B 8,4:58
- Passend:380 [Mate]: 500249:4 ↔ DIN 125-1 B B 8,4:59
- Passend:382 [Mate]: 500249:4 ↔ DIN 125-1 B B 8,4:60
- Passend:384 [Mate]: 500382:7 ↔ DIN 125-1 B B 8,4:61
- Passend:386 [Mate]: 500382:7 ↔ DIN 125-1 B B 8,4:62
- Passend:388 [Mate]: 500382:6 ↔ DIN 125-1 B B 8,4:63
- Passend:390 [Mate]: 500382:6 ↔ DIN 125-1 B B 8,4:64
- Passend:392 [Mate]: 500249:7 ↔ DIN 125-1 B B 8,4:65
- Passend:394 [Mate]: 500249:7 ↔ DIN 125-1 B B 8,4:66
- Passend:396 [Mate]: 500249:8 ↔ DIN 125-1 B B 8,4:67
- Passend:398 [Mate]: 500249:8 ↔ DIN 125-1 B B 8,4:68
- Passend:400 [Mate]: 500382:5 ↔ DIN 125-1 B B 8,4:69
- Passend:402 [Mate]: 500382:5 ↔ DIN 125-1 B B 8,4:70
- Passend:404 [Mate]: DIN 125-1 B B 8,4:70 ↔ ISO 4762 M8 x 16:1
- Einfügen:100 [Insert]: DIN 125-1 B B 8,4:69 ↔ ISO 4762 M8 x 16:2
- Einfügen:101 [Insert]: DIN 125-1 B B 8,4:68 ↔ ISO 4762 M8 x 16:3
- Einfügen:102 [Insert]: DIN 125-1 B B 8,4:67 ↔ ISO 4762 M8 x 16:4
- Einfügen:103 [Insert]: DIN 125-1 B B 8,4:66 ↔ ISO 4762 M8 x 16:5
- Einfügen:104 [Insert]: DIN 125-1 B B 8,4:65 ↔ ISO 4762 M8 x 16:6
- Einfügen:105 [Insert]: DIN 125-1 B B 8,4:64 ↔ ISO 4762 M8 x 16:8
- Einfügen:106 [Insert]: DIN 125-1 B B 8,4:63 ↔ ISO 4762 M8 x 16:7
- Einfügen:107 [Insert]: DIN 125-1 B B 8,4:55 ↔ ISO 4762 M8 x 16:9
- Einfügen:108 [Insert]: DIN 125-1 B B 8,4:56 ↔ ISO 4762 M8 x 16:10
- Einfügen:109 [Insert]: DIN 125-1 B B 8,4:57 ↔ ISO 4762 M8 x 16:11
- Einfügen:110 [Insert]: DIN 125-1 B B 8,4:58 ↔ ISO 4762 M8 x 16:12
- Einfügen:111 [Insert]: DIN 125-1 B B 8,4:59 ↔ ISO 4762 M8 x 16:13
- Einfügen:112 [Insert]: DIN 125-1 B B 8,4:60 ↔ ISO 4762 M8 x 16:14
- Einfügen:113 [Insert]: DIN 125-1 B B 8,4:61 ↔ ISO 4762 M8 x 16:15
- Einfügen:114 [Insert]: DIN 125-1 B B 8,4:62 ↔ ISO 4762 M8 x 16:16
- Einfügen:115 [Insert]: DIN 125-1 B B 8,4:54 ↔ ISO 4762 M8 x 16:17
- Einfügen:116 [Insert]: DIN 125-1 B B 8,4:53 ↔ ISO 4762 M8 x 16:18
- Einfügen:117 [Insert]: DIN 125-1 B B 8,4:52 ↔ ISO 4762 M8 x 16:19
- Einfügen:118 [Insert]: DIN 125-1 B B 8,4:51 ↔ ISO 4762 M8 x 16:20
- Einfügen:119 [Insert]: DIN 125-1 B B 8,4:50 ↔ ISO 4762 M8 x 16:21
- Einfügen:120 [Insert]: DIN 125-1 B B 8,4:49 ↔ ISO 4762 M8 x 16:22
- Einfügen:121 [Insert]: DIN 125-1 B B 8,4:48 ↔ ISO 4762 M8 x 16:23
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## Named parameters: d156_d151 = 0, d157_d152 = 0, d216_d227 = 0, d217_d228 = 0, d218_d209 = 0, d219_d210 = 0, d220_d211 = 0, d221_d212 = 0, d222_d213 = 0, d223_d214 = 0, d224_d215 = 0, d236_d187 = 0, d237_d188 = 0, d238_d189 = 0, d239_d190 = 0, d240_d191 = 0, d241_d192 = 0, d242_d193 = 0, d243_d194 = 0, d244_d195 = 0, d245_d196 = 0, d246_d197 = 0, d247_d198 = 0, d248_d199 = 0, d249_d200 = 0, d250_d201 = 0, d251_d202 = 0, d252_d203 = 0, d253_d204 = 0, d254_d205 = 0, d255_d206 = 0, d256_d207 = 0, d257_d208 = 0, d261_d150 = 0, d262_d151 = 0, d263_d152 = 0, d264_d153 = 0, d265_d154 = 0, d266_d155 = 0, d270_d159 = 0, d271_d160 = 0, d272_d161 = 0, d273_d162 = 0, d274_d163 = 0, d275_d164 = 0, d276_d165 = 0, d277_d166 = 0, d278_d167 = 0, d279_d168 = 0, d280_d169 = 0, d281_d170 = 0, d282_d171 = 0, d283_d172 = 0, d284_d173 = 0, d285_d174 = 0, d286_d175 = 0, d287_d176 = 0, d288_d177 = 0, d289_d178 = 0, d290_d179 = 0, d291_d180 = 0, d292_d181 = 0, d293_d182 = 0, d294_d183 = 0, d295_d184 = 0, d296_d185 = 0, d297_d186 = 0, d298_d116 = 0, d299_d117 = 0, d300_d118 = 0, d301_d119 = 0, d302_d120 = 0, d303_d121 = 0, d305_d123 = 0, d306_d124 = 0, d307_d125 = 0, d329_d89 = 0, d330_d90 = 0, d331_d91 = 0, d332_d92 = 0, d345_d105 = 0, d346_d106 = 0, d347_d107 = 0, d348_d108 = 0, d350_d110 = 0, d352_d112 = 0, d353_d113 = 0, d354_d114 = 0, d355_d115 = 0, d356_d79 = 0, d357_d80 = 0, d358_d81 = 0, d359_d82 = 0, d360_d83 = 0, d361_d84 = 0, d362_d85 = 0, d363_d86 = 0, d364_d87 = 0, d365_d88 = 0, d366_d124 = 2.5 mm, d367_d125 = 2.5 mm, d368_d44 = 0, d369_d45 = 0, d370_d46 = 0, d371_d47 = 0, d372_d67 = 0, d373_d68 = 0, d374_d27 = 0, d398_d13 = 0, d399_d14 = 0, d400_d21 = 0, d401_d22 = 0, width_rails = 482 mm
